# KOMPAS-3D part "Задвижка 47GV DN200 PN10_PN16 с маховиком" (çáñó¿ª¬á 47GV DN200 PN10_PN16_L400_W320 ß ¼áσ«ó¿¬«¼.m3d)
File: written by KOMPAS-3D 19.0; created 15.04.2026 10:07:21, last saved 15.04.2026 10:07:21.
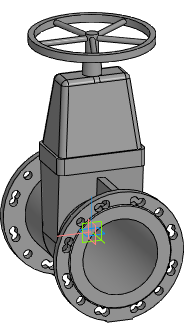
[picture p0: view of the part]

Document properties: Автор: Евгений; Полное имя файла: Z:\3.Личные\kachalov\3d для проектировщиков\2.1 Тип 47GV, 47GV.Z\Задвижка 47GV_DN40-DN600\stp_Задвижка 47GV\Задвижка 47GV DN200 PN10_PN16_L400_W320 с маховиком.m3d

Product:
- Part/product: Задвижка 47GV DN200 PN10_PN16 с маховиком

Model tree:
1. Операция без истории:1  (labels: Задвижка 47GV DN200 PN10_PN16 с маховиком)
